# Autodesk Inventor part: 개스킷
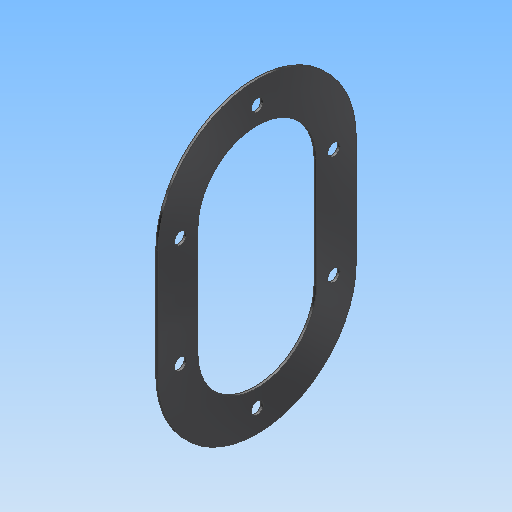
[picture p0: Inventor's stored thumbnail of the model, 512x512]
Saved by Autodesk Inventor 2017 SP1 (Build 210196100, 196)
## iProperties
Created: 2019-03
Part Number: 개스킷
Material: 고무
Document SubType Name: Modeling
Designer: mduedu
Density: 1 g/cm^3
Appearance: 고무 - 검은색 - 버전 1.1
Author: mduedu
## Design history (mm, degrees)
sketch "스케치1"
  geometry: L1 (-62, 40)-(62, 40); L2 (62, 40)-(62, -40); L3 (62, -40)-(-62, -40); L4 (-62, -40)-(-62, 40); L5 (-62, 40)-(62, -40); L6 (62, 40)-(-62, -40); 1 further point
  constraints: 12 end point, 2 midpoint, 2 parallel, 1 horizontal, 1 perpendicular
  dimensions: "d21" = 124 distance of L2.end L3.end; "d22" = 80 distance of L1.end L2.end
extrude "돌출1" new body sketch "스케치1" distance "d3" = 1; taper "d4" = 0 deg
fillet "모깎기2"
fillet "모깎기3"
sketch "스케치2" dims "d6" = 48
  geometry: L1 (-24, -22)-(24, -22); L2 (24, -22)-(24, 22); L3 (24, 22)-(-24, 22); L4 (-24, 22)-(-24, -22); L5 (-24, -22)-(24, 22); L6 (24, -22)-(-24, 22); 3 further points
  constraints: 12 end point, 4 midpoint, 2 horizontal alignment, 2 parallel, 1 horizontal, 1 perpendicular, 4 other
  dimensions: "d8" = 22 distance from line of L3 point (0, 0)
extrude "돌출2" cut sketch "스케치2" stored distance "d9" = 1; taper "d10" = 0 deg
sketch "스케치3"
  geometry: L1 (24, -22)-(24, 22) reference; L2 (-24, 22)-(-24, -22) reference; L3 (31, 22)-(31, -22); L4 (-31, -22)-(-31, 22); A1 r 24 centre (0, 22) between (24, 22) and (-24, 22) reference; A2 r 24 centre (0, -22) between (-24, -22) and (24, -22) reference; A3 r 31 centre (0, 22) between (31, 22) and (-31, 22); A4 r 31 centre (0, -22) between (-31, -22) and (31, -22); 7 further points
  constraints: 6 point on circle, 4 coincident, 4 end point, 2 centre point, 3 other
  dimensions: "d26" = 62 distance between parallel lines of L3 L4; "d28" = 7 distance between parallel lines of L4 L2 (derived); "d29" = 48 distance between parallel lines of L1 L2 (derived); "d30" = 31 radius of A3 (derived)
hole "구멍1" sketch "스케치3" at (0, 53), (31, 22), (31, -22), (0, -53), (-31, -22), (-31, 22) diameter "d14" = 5; stored, may be unused: countersink angle "d18" = 90 deg, drill point angle "d20" = 118 deg; dims "d15" = 6, "d16" = 4, "d17" = 2, "d19" = 8
node "솔리드1"
